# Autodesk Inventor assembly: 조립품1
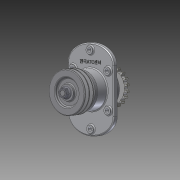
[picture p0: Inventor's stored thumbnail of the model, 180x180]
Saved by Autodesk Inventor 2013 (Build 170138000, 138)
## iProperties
Created: 2015-02
Part Number: 조립품1
Document SubType Name: Assembly
Designer: Administrator
Author: Administrator
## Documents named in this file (12)
- C:\Users\Administrator\Desktop\450208V1013\조립품1.iam
- C:\Users\Administrator\Desktop\450208V1013\2-커버.ipt
- C:\Users\Administrator\Desktop\450208V1013\3-축.ipt
- C:\Users\Administrator\Desktop\450208V1013\4-V벨트풀리.ipt
- C:\Users\Administrator\Desktop\450208V1013\5-체인 스프로킷.ipt
- C:\Users\Administrator\Desktop\450208V1013\6-베어링 6206.ipt
- C:\Users\Administrator\Desktop\450208V1013\7-부시.ipt
- C:\Users\Administrator\Desktop\450208V1013\8-오일실 30x42.ipt
- C:\Users\Administrator\Desktop\450208V1013\9-M16-너트.ipt
- C:\Users\Administrator\Desktop\450208V1013\10-M6.ipt
- C:\Users\Administrator\Desktop\450208V1013\11-키 6x6.ipt
- C:\Users\Administrator\Desktop\450208V1013\본체.ipt
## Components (22 placed, 10 different names)
1. 2-커버:1
2. 3-축:1
3. 4-V벨트풀리:1
4. 5-체인 스프로킷:1
5. 6-베어링 6206:1
6. 7-부시:1
7. 8-8-오일실 30x42:1
8. 9-M16 너트:1
9. 11-키 6x6:1
10. 2-커버:2
11. 11-키 6x6:2
12. 9-M16 너트:2
13. 8-8-오일실 30x42:2
14. 6-베어링 6206:2
15. 10-M6:1
16. 10-M6:3
17. 10-M6:4
18. 10-M6:5
19. 10-M6:2
20. 10-M6:6
21. 10-M6:7
22. 10-M6:8
